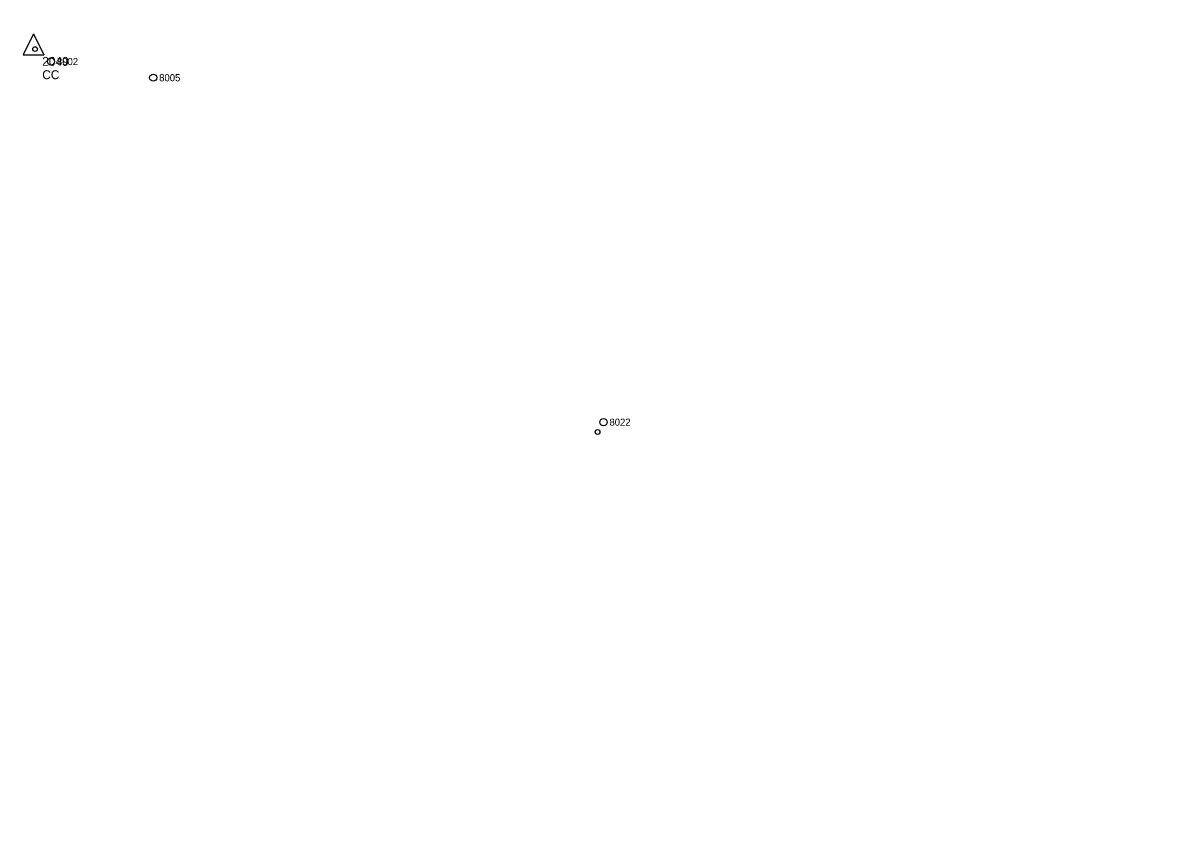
# Model space of a CAD drawing. Extents: x 1674300 to 1677920, y 225056 to 231852.
# Drawn here: x 1675918 to 1676889, y 228324 to 229010 of the extents above; entities that cross this region are included whole.
import ezdxf

# ---------------------------------------------------------------- set-up
doc = ezdxf.new("R2010")
doc.units = 0
for name, color, linetype in [('R_Horz Alg', 7, 'Continuous'), ('R_Horz Alg Annot', 7, 'Continuous'), ('S_CAL_CORNER', 7, 'Continuous'), ('S_CAL_CORNER_ANNOT', 7, 'Continuous'), ('S_EXIST_ROW', 7, 'Continuous')]:
    doc.layers.add(name, color=color, linetype=linetype)

msp = doc.modelspace()

# ---------------------------------------------------------------- linework, layer by layer
at = {"layer": 'R_Horz Alg'}
msp.add_arc((1675928.16, 228988.54), 1449, 296.0624, 0.80558, dxfattribs=at)
at = {"layer": 'R_Horz Alg Annot'}
for centre, radius in [((1675928.16, 228988.54), 2), ((1675941.62, 228978.01), 3), ((1676027.8, 228964.37), 3), ((1676407.49, 228673.82), 3), ((1676402.48, 228665.51), 2)]:
    msp.add_circle(centre, radius, dxfattribs=at)
at = {"layer": 'S_CAL_CORNER'}
for p, q in [((1675926.84, 229001.37), (1675918.02, 228983.64)), ((1675926.84, 229001.37), (1675918.02, 228983.64)), ((1675926.84, 229001.37), (1675918.02, 228983.64)), ((1675926.84, 229001.37), (1675918.02, 228983.64)), ((1675926.84, 229001.37), (1675935.56, 228983.64)), ((1675926.84, 229001.37), (1675935.56, 228983.64)), ((1675926.84, 229001.37), (1675935.56, 228983.64)), ((1675926.84, 229001.37), (1675935.56, 228983.64)), ((1675918.02, 228983.64), (1675935.56, 228983.64)), ((1675918.02, 228983.64), (1675935.56, 228983.64)), ((1675918.02, 228983.64), (1675935.56, 228983.64)), ((1675918.02, 228983.64), (1675935.56, 228983.64))]:
    msp.add_line(p, q, dxfattribs=at)
at = {"layer": 'S_EXIST_ROW'}
msp.add_arc((1675926.71, 228989.39), 1410.53, 295.94359, 0.85682, dxfattribs=at)

# ---------------------------------------------------------------- texts
at = {"layer": 'R_Horz Alg Annot'}
for s, p in [('8002', (1675946.62, 228975.01)), ('8005', (1676032.8, 228961.37)), ('8022', (1676412.49, 228670.82))]:
    msp.add_text(s, height=6, dxfattribs=at).set_placement(p)
at = {"layer": 'S_CAL_CORNER_ANNOT'}
for s, p in [('2049', (1675934.21, 228974.39)), ('2049', (1675934.21, 228974.39)), ('2049', (1675934.21, 228974.39)), ('2049', (1675934.21, 228974.39)), ('CC', (1675934.21, 228963.14)), ('CC', (1675934.21, 228963.14)), ('CC', (1675934.21, 228963.14)), ('CC', (1675934.21, 228963.14))]:
    msp.add_text(s, height=7.5, dxfattribs=at).set_placement(p)

doc.saveas('drawing.dxf')
